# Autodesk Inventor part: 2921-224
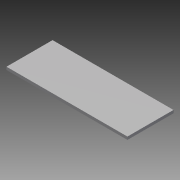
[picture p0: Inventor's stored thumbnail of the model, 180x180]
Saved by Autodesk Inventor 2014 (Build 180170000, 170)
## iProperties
Company: NHTSA/VRTC
Created: 2012-08
Part Number: 2921-224
Material: Steel, Mild
Document SubType Name: Modeling
Designer: Mike Vanvoorhis
Density: 7.86 g/cm^3
Mass: 4564.43 g
Surface Area: 1324.59 cm^2
Volume: 580.717 cm^3
Project: CHILD SIDE IMPACT SLED
Description: IMPACTOR STOP SUPPORT PLATE
Stock Number: PL 9.5 (3/8") x 152.4 (6") x 400.1 (15 3/4")
Appearance: Steel
Author: Dave Walker
Title: Impactor Stop Support Plate
Subject: Child Side Impact Sled
Revision Number: A
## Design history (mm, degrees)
sketch "Sketch1"
  geometry: L1 (0, 0)-(400.05, 0); L2 (400.05, 0)-(400.05, 9.525); L3 (400.05, 9.525)-(0, 9.525); L4 (0, 9.525)-(0, 0)
  constraints: 8 end point, 2 parallel, 1 horizontal, 1 perpendicular
  dimensions: "d0" = 400.05 distance of L3.end L2.end; "d1" = 9.525 distance of L2.end L1.end
extrude "Extrusion1" new body sketch "Sketch1" distance "d2" = 152.4; taper "d3" = 0 deg
body "Solid1"
